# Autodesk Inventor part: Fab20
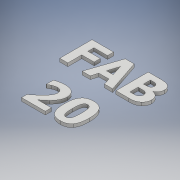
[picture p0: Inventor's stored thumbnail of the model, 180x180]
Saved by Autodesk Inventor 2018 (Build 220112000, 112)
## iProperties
Created: 2020-11
Part Number: Fab20
Material: Genérico
Document SubType Name: Modeling
Designer: ULISES
Density: 1 g/cm^3
Appearance: Valor por defecto
Author: ULISES
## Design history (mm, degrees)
sketch "Boceto1"
  geometry: L1 (0, 0)-(60, 0); L2 (60, 0)-(60, 60); L3 (60, 60)-(0, 60); L4 (0, 60)-(0, 0); L5 (-0.169, 58.552)-(60, 58.552); L6 (60, 58.552)-(60, 0); L7 (60, 0)-(-0.169, 0); L8 (-0.169, 0)-(-0.169, 58.552)
  constraints: 8 end point, 2 parallel, 1 coincident, 1 horizontal, 1 perpendicular, 2 other
  dimensions: "d0" = 60 distance of L3.end L1.start; "d1" = 60 distance of L2.end L3.end
extrude "Extrusión1" new body sketch "Boceto1" distance "d2" = 2; taper "d3" = 0 deg
node "Sólido1"
